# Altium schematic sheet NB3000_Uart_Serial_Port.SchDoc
size A
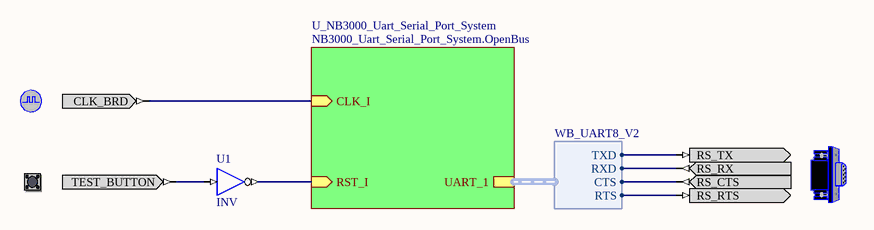
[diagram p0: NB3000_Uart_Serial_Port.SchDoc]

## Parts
(Parts that share a designator on the sheet are numbered #1, #2 ... from top to bottom, then left to right.)
?#1  CLOCK_BOARD  (value not drawn)
?#2  RS232CNTR  (value not drawn)
?#3  TEST_BUTTON  (value not drawn)
U1  INV

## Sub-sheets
U_NB3000_Uart_Serial_Port_System = NB3000_Uart_Serial_Port_System.OpenBus: UART_1 (harness WB_UART8_V2), RST_I (in), CLK_I (in)

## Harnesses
WB_UART8_V2: TXD, RXD, CTS, RTS

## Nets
Net?#1_CLK_BRD: ?#1.CLK_BRD ; sheet U_NB3000_Uart_Serial_Port_System/CLK_I
Net?#2_RS_CTS: ?#2.RS_CTS ; sheet U_NB3000_Uart_Serial_Port_System/UART_1.CTS
Net?#2_RS_RTS: ?#2.RS_RTS ; sheet U_NB3000_Uart_Serial_Port_System/UART_1.RTS
Net?#2_RS_RX: ?#2.RS_RX ; sheet U_NB3000_Uart_Serial_Port_System/UART_1.RXD
Net?#2_RS_TX: ?#2.RS_TX ; sheet U_NB3000_Uart_Serial_Port_System/UART_1.TXD
Net?#3_TEST_BUTTON: ?#3.TEST_BUTTON U1.I
NetU1_O: U1.O ; sheet U_NB3000_Uart_Serial_Port_System/RST_I

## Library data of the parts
?#1 = CLOCK_BOARD: Global System Clock Supply; PortComponent: True
?#2 = RS232CNTR: DCE Serial Port Connector; PortComponent: True
?#3 = TEST_BUTTON: Test / Reset Button; PortComponent: True
U1 = INV: Inverter; FunctionalClass: Logic Primitive; ArchiveName: GENERIC; VHDLIB_SIM: GENERIC_LIB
